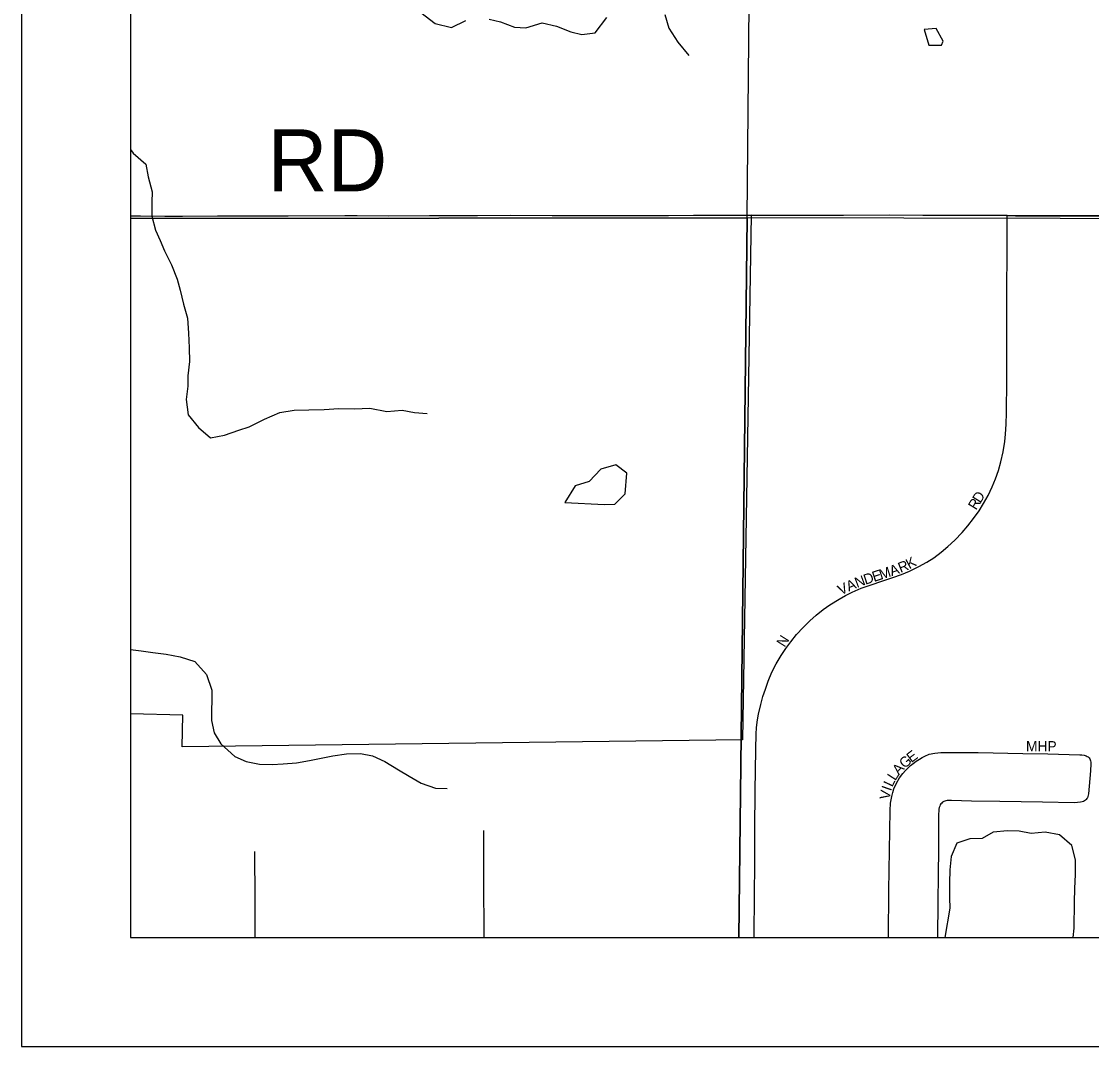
# Model space of a CAD drawing. Extents: x 0 to 1391, y -24 to 440.
# Drawn here: x 490 to 509.64, y 280 to 298.81 of the extents above; entities that cross this region are included whole.
import ezdxf

# ---------------------------------------------------------------- set-up
doc = ezdxf.new("R2010")
doc.units = 0
for name, color, linetype in [('GM_X_City_Street', 7, 'Continuous'), ('GM_X_City_Street_Text', 7, 'Continuous'), ('GM_X_Corporation', 7, 'Continuous'), ('GM_X_Minor_Lake', 7, 'Continuous'), ('GM_X_Minor_River', 7, 'Continuous'), ('GM_X_Section', 7, 'Continuous'), ('GM_X_Township', 7, 'Continuous'), ('GM_X_Township_Road', 7, 'Continuous'), ('GM_X_Township_Road_Text', 7, 'Continuous'), ('SH_Data', 7, 'Continuous')]:
    doc.layers.add(name, color=color, linetype=linetype)

msp = doc.modelspace()

# ---------------------------------------------------------------- linework, layer by layer
at = {"layer": 'GM_X_City_Street'}
for points in [[(503.51, 285.995), (503.529, 286.101), (503.568, 286.275), (503.608, 286.423), (503.654, 286.56), (503.706, 286.706), (503.773, 286.872), (503.849, 287.023), (503.944, 287.175), (504.028, 287.303), (504.122, 287.43), (504.227, 287.563), (504.345, 287.69), (504.47, 287.811), (504.583, 287.918), (504.711, 288.019), (504.836, 288.109), (505.007, 288.213), (505.121, 288.279), (505.244, 288.336), (505.412, 288.409), (505.558, 288.463), (505.826, 288.55), (505.993, 288.605), (506.153, 288.661), (506.299, 288.722), (506.472, 288.809), (506.616, 288.891), (506.742, 288.969), (506.88, 289.071), (507.002, 289.174), (507.128, 289.291), (507.265, 289.432), (507.37, 289.553), (507.476, 289.688), (507.575, 289.828), (507.659, 289.964), (507.741, 290.115), (507.815, 290.27), (507.876, 290.417), (507.929, 290.568), (507.977, 290.733), (508.019, 290.912), (508.047, 291.101), (508.063, 291.24), (508.075, 291.422), (508.08, 291.632), (508.082, 292.229), (508.082, 293.133), (508.083, 293.498), (508.089, 294.945), (508.09, 295.098), (508.09, 295.249)], [(503.449, 282), (503.449, 282.023), (503.456, 282.789), (503.46, 283.34), (503.46, 283.994), (503.466, 284.686), (503.479, 285.449), (503.485, 285.742), (503.491, 285.848), (503.503, 285.955), (503.51, 285.995)], [(505.914, 282), (505.914, 282.006), (505.918, 282.864), (505.942, 284.331), (505.952, 284.469), (505.972, 284.592), (505.992, 284.665), (506.012, 284.727), (506.059, 284.831), (506.116, 284.93), (506.176, 285.012), (506.224, 285.066), (506.271, 285.113), (506.319, 285.156), (506.366, 285.197), (506.423, 285.238), (506.479, 285.277), (506.531, 285.307), (506.579, 285.332), (506.662, 285.364), (506.762, 285.387), (506.875, 285.398), (507.137, 285.399), (507.56, 285.394), (508.38, 285.376), (508.84, 285.37), (509.425, 285.356), (509.464, 285.352), (509.502, 285.347), (509.522, 285.342), (509.541, 285.336), (509.561, 285.325), (509.578, 285.314), (509.595, 285.298), (509.606, 285.282), (509.615, 285.263), (509.621, 285.242), (509.626, 285.217), (509.628, 285.189), (509.623, 285.062), (509.585, 284.639), (509.58, 284.615), (509.573, 284.588), (509.564, 284.567), (509.555, 284.55), (509.541, 284.533), (509.526, 284.519), (509.51, 284.508), (509.49, 284.497), (509.465, 284.489), (509.437, 284.483), (509.38, 284.478), (509.323, 284.475), (508.739, 284.483), (507.955, 284.495), (507.434, 284.506), (507.071, 284.514), (506.988, 284.513), (506.967, 284.51), (506.945, 284.504), (506.926, 284.495), (506.906, 284.483), (506.891, 284.469), (506.875, 284.452), (506.864, 284.434), (506.853, 284.413), (506.844, 284.388), (506.838, 284.357), (506.833, 284.236), (506.829, 283.777), (506.829, 283.626), (506.824, 283.147), (506.819, 282.658), (506.814, 282)], [(498.494, 282), (498.487, 283.091), (498.487, 283.963)], [(494.287, 282), (494.287, 282.348), (494.288, 282.695), (494.285, 283.581)]]:
    msp.add_lwpolyline(points, dxfattribs=at)
at = {"layer": 'GM_X_Corporation'}
for points in [[(511.877, 298.895), (511.78, 297.253), (511.618, 295.243), (508.09, 295.249), (503.394, 295.259), (503.233, 285.631), (492.952, 285.499), (492.96, 286.083), (492, 286.106)], [(492, 286.106), (492, 282), (569.105, 282)]]:
    msp.add_lwpolyline(points, dxfattribs=at)
at = {"layer": 'GM_X_Minor_Lake'}
for p, q in [((506.565, 298.663), (506.651, 298.373)), ((506.884, 298.373), (506.918, 298.451))]:
    msp.add_line(p, q, dxfattribs=at)
for points in [[(506.918, 298.451), (506.785, 298.681), (506.565, 298.663)], [(506.651, 298.373), (506.884, 298.373)], [(501.081, 290.141), (501.111, 290.52), (500.909, 290.676), (500.634, 290.598), (500.417, 290.367), (500.165, 290.289), (499.976, 289.981)], [(499.976, 289.981), (500.699, 289.945), (500.889, 289.956), (501.081, 290.141)], [(509.329, 282.652), (509.333, 282.902), (509.345, 283.16), (509.342, 283.425), (509.279, 283.691), (509.054, 283.885), (508.789, 283.936), (508.53, 283.911), (508.31, 283.954), (508.097, 283.958), (507.831, 283.933), (507.631, 283.816), (507.403, 283.813), (507.166, 283.735), (507.063, 283.487), (507.036, 283.245), (507.032, 283.002), (507.035, 282.729), (507.039, 282.54)], [(509.301, 282), (509.321, 282.175), (509.329, 282.652)], [(507.039, 282.54), (506.944, 282)]]:
    msp.add_lwpolyline(points, dxfattribs=at)
at = {"layer": 'GM_X_Minor_River'}
for points in [[(497.329, 298.973), (497.593, 298.772), (497.896, 298.699), (498.156, 298.831)], [(501.808, 298.941), (501.881, 298.689), (502.046, 298.429), (502.248, 298.183)], [(498.583, 298.855), (498.795, 298.806), (499.052, 298.704), (499.258, 298.693), (499.555, 298.787), (499.821, 298.722), (500.086, 298.619), (500.283, 298.57), (500.527, 298.604), (500.743, 298.882)], [(492, 296.463), (492.05, 296.394), (492.283, 296.193), (492.326, 295.957), (492.399, 295.683), (492.396, 295.494), (492.393, 295.236), (492.458, 294.984), (492.547, 294.793), (492.629, 294.603), (492.755, 294.343), (492.858, 294.083), (492.916, 293.877), (492.974, 293.626), (493.047, 293.367), (493.066, 293.094), (493.078, 292.821), (493.083, 292.57), (493.057, 292.305), (493.054, 292.116), (493.021, 291.873), (493.063, 291.592), (493.25, 291.362), (493.469, 291.169), (493.728, 291.218), (493.988, 291.312), (494.178, 291.37), (494.462, 291.51), (494.744, 291.634), (495.004, 291.675), (495.277, 291.686), (495.559, 291.69), (495.825, 291.708), (496.114, 291.704), (496.396, 291.714), (496.707, 291.656), (496.989, 291.675), (497.216, 291.633), (497.444, 291.614)], [(492, 287.285), (492.198, 287.26), (492.411, 287.233), (492.654, 287.199), (492.912, 287.149)], [(492.912, 287.149), (493.185, 287.069), (493.394, 286.83), (493.496, 286.54), (493.487, 285.986), (493.536, 285.757), (493.662, 285.557), (493.918, 285.325), (494.122, 285.231), (494.372, 285.181), (494.6, 285.177), (494.806, 285.189), (495.05, 285.208), (495.287, 285.25), (495.714, 285.333), (495.966, 285.375), (496.225, 285.378), (496.445, 285.337), (496.672, 285.234), (496.921, 285.078), (497.117, 284.961), (497.335, 284.836), (497.6, 284.74), (497.813, 284.737)]]:
    msp.add_lwpolyline(points, dxfattribs=at)
at = {"layer": 'GM_X_Section'}
for p, q in [((492, 315.332), (492, 295.194)), ((503.169, 282), (523.404, 282))]:
    msp.add_line(p, q, dxfattribs=at)
for points in [[(492, 295.194), (503.319, 295.209), (503.508, 315.416), (492, 315.332)], [(503.169, 282), (503.319, 295.209), (492, 295.194)], [(492, 295.194), (492, 282), (503.169, 282)], [(523.404, 282), (523.431, 295.166), (503.319, 295.209), (503.169, 282)]]:
    msp.add_lwpolyline(points, dxfattribs=at)
msp.add_lwpolyline([(503.508, 315.416), (515.053, 315.041), (523.385, 314.999), (523.431, 295.166), (503.319, 295.209)], close=True, dxfattribs=at)
at = {"layer": 'GM_X_Township'}
msp.add_lwpolyline([(492, 315.227), (492, 282), (569.034, 282)], dxfattribs=at)
at = {"layer": 'GM_X_Township_Road'}
for points in [[(492, 295.243), (492.185, 295.242), (492.632, 295.238), (492.955, 295.238), (493.601, 295.243), (494.135, 295.245), (494.893, 295.244), (495.937, 295.252), (496.161, 295.252), (496.732, 295.247), (497.49, 295.248), (498.372, 295.249), (498.981, 295.254), (499.739, 295.251), (500.509, 295.251), (501.18, 295.251), (501.876, 295.253), (502.335, 295.254)], [(502.335, 295.254), (502.783, 295.255), (503.143, 295.257), (503.395, 295.259)], [(503.395, 295.259), (504.13, 295.259), (505.086, 295.257), (505.931, 295.26), (506.541, 295.259), (507.137, 295.257), (507.871, 295.254), (508.09, 295.249)], [(508.09, 295.249), (508.243, 295.245), (508.632, 295.243)], [(508.632, 295.243), (508.827, 295.242), (509.498, 295.244), (510.107, 295.243), (510.629, 295.241), (510.995, 295.241), (511.213, 295.242), (511.344, 295.242), (511.618, 295.243)]]:
    msp.add_lwpolyline(points, dxfattribs=at)
at = {"layer": 'SH_Data'}
for p, q in [((490, 420), (490, 280)), ((492, 418), (492, 282)), ((492, 418), (492, 282)), ((492, 282), (628, 282)), ((492, 282), (628, 282)), ((490, 280), (630, 280))]:
    msp.add_line(p, q, dxfattribs=at)

# ---------------------------------------------------------------- texts
at = {"layer": 'GM_X_City_Street_Text'}
for s, height, rotation, p in [('D', 0.189, 58.6502, (507.6, 289.96)), ('R', 0.189, 58.6614, (507.522, 289.832)), ('R', 0.189, 21.9303, (506.134, 288.69)), ('K', 0.189, 28.4854, (506.295, 288.756)), ('E', 0.189, 17.9424, (505.647, 288.525)), ('M', 0.189, 18.1695, (505.775, 288.566)), ('A', 0.189, 19.8023, (505.97, 288.63)), ('V', 0.189, 25.0697, (505.035, 288.278)), ('A', 0.189, 23.9248, (505.185, 288.348)), ('N', 0.189, 20.7582, (505.335, 288.415)), ('D', 0.189, 18.0686, (505.489, 288.473)), ('N', 0.189, 57.9872, (504.005, 287.316)), ('MHP', 0.1894, 0, (508.436, 285.416)), ('E', 0.189, 37.1322, (506.333, 285.201)), ('G', 0.189, 41.2723, (506.21, 285.093)), ('L', 0.189, 57.3025, (506.036, 284.867)), ('A', 0.189, 48.2321, (506.103, 284.973)), ('I', 0.189, 70.5697, (505.957, 284.678)), ('L', 0.189, 64.9138, (505.983, 284.752)), ('V', 0.189, 80.8251, (505.933, 284.522))]:
    msp.add_text(s, height=height, rotation=rotation, dxfattribs=at).set_placement(p)
at = {"layer": 'GM_X_Township_Road_Text'}
msp.add_text('RD', height=1.1364, rotation=0, dxfattribs=at).set_placement((494.519, 295.694))

doc.saveas('drawing.dxf')
